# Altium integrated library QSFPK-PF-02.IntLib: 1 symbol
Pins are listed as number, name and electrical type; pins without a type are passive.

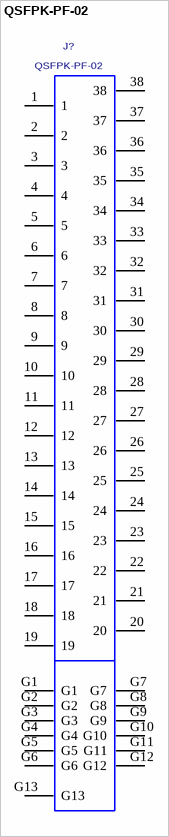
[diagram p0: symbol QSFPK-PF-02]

## QSFPK-PF-02
designator J?
QSFP Assembly With Heat Sink.; MANUFACTURER: SAMTEC
footprint QSFPK-PF-02
pins: 1, 2, 3, 4, 5, 6, 7, 8, 9, 10, 11, 12, 13, 14, 15, 16, 17, 18, 19, 20, 21, 22, 23, 24, 25, 26, 27, 28, 29, 30, 31, 32, 33, 34, 35, 36, 37, 38, G1, G2, G3, G4, G5, G6, G7, G8, G9, G10, G11, G12, G13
